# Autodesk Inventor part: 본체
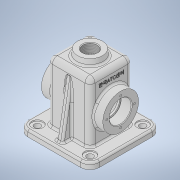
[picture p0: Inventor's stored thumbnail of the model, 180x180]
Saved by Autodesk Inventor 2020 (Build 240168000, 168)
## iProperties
Created: 2021-07
Part Number: 본체
Material: 일반
Document SubType Name: Modeling
Designer: Owner
Density: 1 g/cm^3
Appearance: 기본값
Mass: 278.261 g
Surface Area: 858.222 cm^2
Volume: 278.261 cm^3
Author: Owner
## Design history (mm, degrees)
sketch "스케치1"
  geometry: L1 (-34, -34)-(34, -34); L2 (34, -34)-(34, 34); L3 (34, 34)-(-34, 34); L4 (-34, 34)-(-34, -34); L5 (-34, -34)-(34, 34); L6 (34, -34)-(-34, 34); 1 further point
  constraints: 12 end point, 2 midpoint, 2 parallel, 1 horizontal, 1 perpendicular
  dimensions: "d0" = 68 distance of L3.end L2.end; "d1" = 68 distance of L2.end L1.end
extrude "돌출1" new body sketch "스케치1" stored distance "d2" = 105; taper "d3" = 0 deg
fillet "모깎기1" dims "d4" = 8
fillet "모깎기2" dims "d5" = 8
feature "쉘1" dims "d6" = 5
sketch "스케치3"
  geometry: L1 (57, -57)-(-57, -57); L2 (-57, -57)-(-57, 57); L3 (-57, 57)-(57, 57); L4 (57, 57)-(57, -57); L5 (57, -57)-(-57, 57); L6 (-57, -57)-(57, 57); L7 (29, 26)-(29, -26) reference; L8 (26, -29)-(-26, -29) reference; L9 (-29, -26)-(-29, 26) reference; L10 (-26, 29)-(26, 29) reference; L11 (26, 34)-(-26, 34) reference; L12 (-34, 26)-(-34, -26) reference; L13 (-26, -34)-(26, -34) reference; L14 (34, -26)-(34, 26) reference; A1 r 3 centre (26, 26) between (29, 26) and (26, 29) reference; A2 r 3 centre (26, -26) between (26, -29) and (29, -26) reference; A3 r 3 centre (-26, -26) between (-29, -26) and (-26, -29) reference; A4 r 3 centre (-26, 26) between (-26, 29) and (-29, 26) reference; A5 r 8 centre (26, 26) between (34, 26) and (26, 34) reference; A6 r 8 centre (-26, 26) between (-26, 34) and (-34, 26) reference; A7 r 8 centre (-26, -26) between (-34, -26) and (-26, -34) reference; A8 r 8 centre (26, -26) between (26, -34) and (34, -26) reference; 1 further point
  constraints: 12 end point, 2 midpoint, 2 parallel, 1 horizontal, 1 perpendicular
  dimensions: "d9" = 114 distance of L2.end L3.end; "d10" = 114 distance of L1.end L2.end
extrude "돌출2" join sketch "스케치3" distance "d11" = 10; taper "d12" = 0 deg
fillet "모깎기3" dims "d13" = 15
fillet "모깎기4" dims "d14" = 15
node "작업 평면1"
sketch "스케치4"
  geometry: L1 (68, -97)-(-16, -97) reference; C1 r 28.5 at (26, -45); 1 further point
  constraints: 1 centre point, 1 vertical alignment
  dimensions: "d16" = 57 diameter of C1; "d17" = 52 distance from line of C1.centre L1
extrude "돌출3" join sketch "스케치4" stored distance "d18" = 10; taper "d19" = 0 deg
sketch "스케치5"
  geometry: C1 r 28.5 at (0, 0) reference; 2 further points
  constraints: 1 coincident
hole "구멍1" sketch "스케치5" at (0, 0) diameter "d20" = 35; stored, may be unused: countersink angle "d24" = 90 deg, drill point angle "d26" = 0 deg; dims "d21" = 20, "d22" = 4, "d23" = 2, "d25" = 17
sketch "스케치6"
  geometry: C1 r 17.5 at (0, 0) reference; 2 further points
  constraints: 1 coincident
hole "구멍2" sketch "스케치6" at (0, 0) diameter "d27" = 30; stored, may be unused: countersink angle "d31" = 90 deg, drill point angle "d33" = 0 deg; dims "d28" = 20, "d29" = 4, "d30" = 2, "d32" = 132.5
node "작업 평면2"
sketch "스케치7"
  geometry: C1 r 20 at (0, 0); 1 further point
  constraints: 1 centre point, 1 coincident
  dimensions: "d35" = 40 diameter of C1
extrude "돌출4" join sketch "스케치7" stored distance "d36" = 10; taper "d37" = 8 deg
sketch "스케치8"
  geometry: C1 r 20 at (0, 0) reference; 2 further points
  constraints: 1 coincident
hole "구멍3" sketch "스케치8" at (0, 0) diameter "d38" = 22.83494; stored, may be unused: countersink angle "d42" = 90 deg, drill point angle "d44" = 0 deg; dims "d39" = 50, "d40" = 4, "d41" = 2, "d43" = 59.3
sketch "스케치9"
  geometry: C1 r 15 at (0, 0) reference; 2 further points
  constraints: 1 vertical alignment
  dimensions: "d45" = 22 distance of point (0, 22) C1.centre
hole "구멍4" sketch "스케치9" at (0, 22) diameter "d46" = 3.242; stored, may be unused: countersink angle "d50" = 90 deg, drill point angle "d52" = 118 deg; dims "d47" = 8, "d48" = 4, "d49" = 2, "d51" = 10
sketch "스케치10"
  geometry: A1 r 15 centre (-42, 42) between (-42, 57) and (-57, 42) reference; 1 further point
hole "구멍5" sketch "스케치10" at (-42, 42) diameter "d56" = 10; stored, may be unused: countersink angle "d60" = 90 deg, drill point angle "d62" = 0 deg; dims "d57" = 8, "d58" = 18, "d59" = 2, "d61" = 35
sketch "스케치11"
  geometry: L1 (-49, -42.5)-(-34, 42.569); L2 (34, 42.569)-(49, -42.5); L3 (-51, -42.5)-(-33, -42.5) reference; L4 (-57, -52.5)-(-57, -42.5) reference; L5 (-34, -42.5)-(-34, 44.5) reference; L6 (33, -42.5)-(51, -42.5) reference; L7 (57, -42.5)-(57, -52.5) reference; L8 (34, 44.5)-(34, -42.5) reference; 1 further point
  constraints: 4 end point, 4 point on line
  dimensions: "d63" = 8 distance from line of L1.start L4; "d64" = 10 deg angle of L1 L4; "d65" = 8 distance from line of L7 L2.end; "d66" = 10 deg angle of L7 L2
sketch "스케치12"
  geometry: L1 (46, 18)-(6, 18) reference; 2 further points
  constraints: 1 vertical alignment, 1 other
  dimensions: "d67" = 25 distance from line of point (26, -7) L1
extrude "돌출5" join sketch "스케치11" stored distance "d68" = 10; taper "d69" = 0 deg
feature "엠보싱1" dims "d70" = 0.5, "d71" = 0
fillet "모깎기5" dims "d72" = 3
fillet "모깎기7" dims "d74" = 3
fillet "모깎기8" dims "d75" = 3
fillet "모깎기9" dims "d76" = 3
fillet "모깎기10" dims "d77" = 3
fillet "모깎기11" dims "d78" = 3
fillet "모깎기12" dims "d79" = 3
chamfer "모따기1" distance "d80" = 1; stored, may be unused: second distance "d81" = 2, angle "d82" = 45 deg
fillet "모깎기13" dims "d83" = 0.3
node "솔리드1"
mirror "미러1"
mirror "미러2"
pattern_circular "원형 패턴1" dims angle "d54" = 360 deg
mirror "미러3"
mirror "미러4"
mirror "미러5"
node "투영된 루프1"
feature "A9D066F2-1C7D-4E18-AEED-F7BC21143FA4" dims "d20" = 35, "d21" = 20, "d22" = 4, "d23" = 2, "d24" = 90 deg, "d25" = 17, "d26" = 0
other parameters: "d15" = 15, "d34" = -115
